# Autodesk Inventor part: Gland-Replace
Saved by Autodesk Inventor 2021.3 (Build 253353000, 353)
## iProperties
Created: 2023-07
Part Number: Gland-Replace
Material: Generic
Document SubType Name: Modeling
Designer: AdminForWorker
Density: 1 g/cm^3
Appearance: Default
Title: Gland-Replace v10
Author: AdminForWorker
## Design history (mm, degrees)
feature "Bend-Out-Wide"
body "Solid1"
